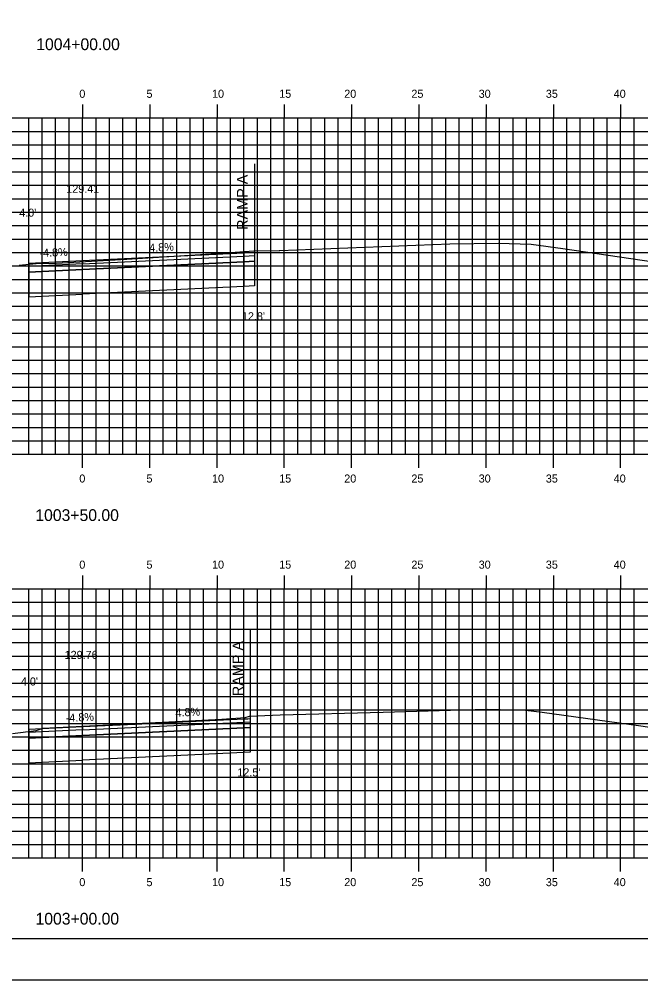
# Model space of a CAD drawing. Extents: x 851073 to 851245, y 365624 to 365734.
# Drawn here: x 851151.5 to 851197.8, y 365624 to 365695.4 of the extents above; entities that cross this region are included whole.
import ezdxf

# ---------------------------------------------------------------- set-up
doc = ezdxf.new("R2010")
doc.units = 0
for name, color, linetype in [('ANNOTATION', 7, 'Continuous'), ('BORDER', 7, 'Continuous'), ('D_Roadway_Centerline', 7, 'Continuous'), ('D_Roadway_Centerline_Text', 7, 'Continuous'), ('D_Roadway_Edge_Shoulder', 7, 'Continuous'), ('D_Roadway_Pavement', 7, 'Continuous'), ('D_Roadway_SubGrade', 7, 'Continuous'), ('D_Text_Standard', 7, 'Continuous'), ('H_V ANNOTATION', 7, 'Continuous'), ('M_Roadway_Centerline', 7, 'Continuous'), ('MAJOR', 7, 'Continuous'), ('MINOR', 7, 'Continuous'), ('PLOT BOUNDARY', 7, 'Continuous'), ('S_Roadway_Centerline', 7, 'Continuous')]:
    doc.layers.add(name, color=color, linetype=linetype)

msp = doc.modelspace()

# ---------------------------------------------------------------- linework, layer by layer
at = {"layer": 'BORDER'}
msp.add_lwpolyline([(851081.253, 365627.027), (851241.253, 365627.027), (851241.253, 365732.027), (851081.253, 365732.027)], close=True, dxfattribs=at)
at = {"layer": 'D_Roadway_Centerline'}
for points in [[(851152.252, 365677.242), (851156.253, 365677.434), (851156.257, 365677.434), (851168.253, 365678.01), (851169.039, 365678.048)], [(851152.252, 365642.595), (851156.252, 365642.787), (851160.165, 365642.975), (851168.244, 365643.362), (851168.252, 365643.363), (851168.549, 365643.377), (851168.706, 365643.384)]]:
    msp.add_lwpolyline(points, dxfattribs=at)
at = {"layer": 'D_Roadway_Edge_Shoulder'}
for p, q in [((851168.253, 365678.01), (851168.253, 365677.76)), ((851156.253, 365677.434), (851156.253, 365677.184)), ((851168.252, 365643.363), (851168.252, 365643.113)), ((851156.252, 365642.787), (851156.252, 365642.537))]:
    msp.add_line(p, q, dxfattribs=at)
at = {"layer": 'D_Roadway_Pavement'}
for points in [[(851156.251, 365677.184), (851168.251, 365677.76), (851168.251, 365677.343), (851156.251, 365676.767)], [(851156.251, 365677.184), (851152.251, 365676.992), (851152.251, 365676.575), (851156.251, 365676.767)], [(851156.251, 365642.537), (851168.251, 365643.113), (851168.251, 365642.696), (851156.251, 365642.12)], [(851156.251, 365642.537), (851152.25, 365642.345), (851152.25, 365641.928), (851156.251, 365642.12)]]:
    msp.add_lwpolyline(points, close=True, dxfattribs=at)
for points in [[(851169.038, 365677.381), (851168.251, 365677.343), (851168.251, 365677.76), (851169.038, 365677.798)], [(851168.707, 365642.718), (851168.251, 365642.696), (851168.251, 365643.113), (851168.707, 365643.135)]]:
    msp.add_lwpolyline(points, dxfattribs=at)
at = {"layer": 'D_Roadway_SubGrade'}
for p, q in [((851169.038, 365684.628), (851169.038, 365677.881)), ((851169.038, 365677.881), (851169.038, 365675.548)), ((851168.707, 365649.965), (851168.707, 365643.218)), ((851168.707, 365643.218), (851168.707, 365640.885))]:
    msp.add_line(p, q, dxfattribs=at)
for points in [[(851156.251, 365676.767), (851152.251, 365676.575), (851152.251, 365677.075), (851152.251, 365677.242), (851152.251, 365674.742), (851156.251, 365674.934)], [(851156.251, 365676.767), (851168.251, 365677.343), (851168.251, 365675.51), (851156.251, 365674.934)], [(851156.251, 365642.12), (851152.25, 365641.928), (851152.25, 365642.428), (851152.25, 365642.595), (851152.25, 365640.095), (851156.251, 365640.287)], [(851156.251, 365642.12), (851168.251, 365642.696), (851168.251, 365640.863), (851156.251, 365640.287)]]:
    msp.add_lwpolyline(points, close=True, dxfattribs=at)
for points in [[(851169.038, 365675.548), (851168.251, 365675.51), (851168.251, 365677.343), (851169.038, 365677.381)], [(851168.707, 365640.885), (851168.251, 365640.863), (851168.251, 365642.696), (851168.707, 365642.718)]]:
    msp.add_lwpolyline(points, dxfattribs=at)
at = {"layer": 'MAJOR'}
for p, q in [((851156.253, 365689.029), (851156.253, 365688.027)), ((851161.253, 365689.029), (851161.253, 365688.027)), ((851166.253, 365689.029), (851166.253, 365688.027)), ((851171.253, 365689.029), (851171.253, 365688.027)), ((851176.253, 365689.029), (851176.253, 365688.027)), ((851181.253, 365689.029), (851181.253, 365688.027)), ((851186.253, 365689.029), (851186.253, 365688.027)), ((851191.253, 365689.029), (851191.253, 365688.027)), ((851196.253, 365689.029), (851196.253, 365688.027)), ((851086.253, 365688.027), (851226.253, 365688.027)), ((851086.253, 365688.027), (851226.253, 365688.027)), ((851156.253, 365663.027), (851156.253, 365688.027)), ((851161.253, 365663.027), (851161.253, 365688.027)), ((851166.253, 365663.027), (851166.253, 365688.027)), ((851171.253, 365663.027), (851171.253, 365688.027)), ((851176.253, 365663.027), (851176.253, 365688.027)), ((851181.253, 365663.027), (851181.253, 365688.027)), ((851186.253, 365663.027), (851186.253, 365688.027)), ((851191.253, 365663.027), (851191.253, 365688.027)), ((851196.253, 365663.027), (851196.253, 365688.027)), ((851086.253, 365683.027), (851226.253, 365683.027)), ((851086.253, 365678.027), (851226.253, 365678.027)), ((851086.253, 365673.027), (851226.253, 365673.027)), ((851086.253, 365668.027), (851226.253, 365668.027)), ((851086.253, 365663.027), (851226.253, 365663.027)), ((851086.253, 365663.027), (851226.253, 365663.027)), ((851156.253, 365662.025), (851156.253, 365663.027)), ((851161.253, 365662.025), (851161.253, 365663.027)), ((851166.253, 365662.025), (851166.253, 365663.027)), ((851171.253, 365662.025), (851171.253, 365663.027)), ((851176.253, 365662.025), (851176.253, 365663.027)), ((851181.253, 365662.025), (851181.253, 365663.027)), ((851186.253, 365662.025), (851186.253, 365663.027)), ((851191.253, 365662.025), (851191.253, 365663.027)), ((851196.253, 365662.025), (851196.253, 365663.027)), ((851156.253, 365654.029), (851156.253, 365653.027)), ((851161.253, 365654.029), (851161.253, 365653.027)), ((851166.253, 365654.029), (851166.253, 365653.027)), ((851171.253, 365654.029), (851171.253, 365653.027)), ((851176.253, 365654.029), (851176.253, 365653.027)), ((851181.253, 365654.029), (851181.253, 365653.027)), ((851186.253, 365654.029), (851186.253, 365653.027)), ((851191.253, 365654.029), (851191.253, 365653.027)), ((851196.253, 365654.029), (851196.253, 365653.027)), ((851086.253, 365653.027), (851226.253, 365653.027)), ((851086.253, 365653.027), (851226.253, 365653.027)), ((851156.253, 365633.027), (851156.253, 365653.027)), ((851161.253, 365633.027), (851161.253, 365653.027)), ((851166.253, 365633.027), (851166.253, 365653.027)), ((851171.253, 365633.027), (851171.253, 365653.027)), ((851176.253, 365633.027), (851176.253, 365653.027)), ((851181.253, 365633.027), (851181.253, 365653.027)), ((851186.253, 365633.027), (851186.253, 365653.027)), ((851191.253, 365633.027), (851191.253, 365653.027)), ((851196.253, 365633.027), (851196.253, 365653.027)), ((851086.253, 365648.027), (851226.253, 365648.027)), ((851086.253, 365643.027), (851226.253, 365643.027)), ((851086.253, 365638.027), (851226.253, 365638.027)), ((851086.253, 365633.027), (851226.253, 365633.027)), ((851086.253, 365633.027), (851226.253, 365633.027)), ((851156.253, 365632.025), (851156.253, 365633.027)), ((851161.253, 365632.025), (851161.253, 365633.027)), ((851166.253, 365632.025), (851166.253, 365633.027)), ((851171.253, 365632.025), (851171.253, 365633.027)), ((851176.253, 365632.025), (851176.253, 365633.027)), ((851181.253, 365632.025), (851181.253, 365633.027)), ((851186.253, 365632.025), (851186.253, 365633.027)), ((851191.253, 365632.025), (851191.253, 365633.027)), ((851196.253, 365632.025), (851196.253, 365633.027))]:
    msp.add_line(p, q, dxfattribs=at)
at = {"layer": 'MINOR'}
for p, q in [((851152.253, 365663.027), (851152.253, 365688.027)), ((851153.253, 365663.027), (851153.253, 365688.027)), ((851154.253, 365663.027), (851154.253, 365688.027)), ((851155.253, 365663.027), (851155.253, 365688.027)), ((851157.253, 365663.027), (851157.253, 365688.027)), ((851158.253, 365663.027), (851158.253, 365688.027)), ((851159.253, 365663.027), (851159.253, 365688.027)), ((851160.253, 365663.027), (851160.253, 365688.027)), ((851162.253, 365663.027), (851162.253, 365688.027)), ((851163.253, 365663.027), (851163.253, 365688.027)), ((851164.253, 365663.027), (851164.253, 365688.027)), ((851165.253, 365663.027), (851165.253, 365688.027)), ((851167.253, 365663.027), (851167.253, 365688.027)), ((851168.253, 365663.027), (851168.253, 365688.027)), ((851169.253, 365663.027), (851169.253, 365688.027)), ((851170.253, 365663.027), (851170.253, 365688.027)), ((851172.253, 365663.027), (851172.253, 365688.027)), ((851173.253, 365663.027), (851173.253, 365688.027)), ((851174.253, 365663.027), (851174.253, 365688.027)), ((851175.253, 365663.027), (851175.253, 365688.027)), ((851177.253, 365663.027), (851177.253, 365688.027)), ((851178.253, 365663.027), (851178.253, 365688.027)), ((851179.253, 365663.027), (851179.253, 365688.027)), ((851180.253, 365663.027), (851180.253, 365688.027)), ((851182.253, 365663.027), (851182.253, 365688.027)), ((851183.253, 365663.027), (851183.253, 365688.027)), ((851184.253, 365663.027), (851184.253, 365688.027)), ((851185.253, 365663.027), (851185.253, 365688.027)), ((851187.253, 365663.027), (851187.253, 365688.027)), ((851188.253, 365663.027), (851188.253, 365688.027)), ((851189.253, 365663.027), (851189.253, 365688.027)), ((851190.253, 365663.027), (851190.253, 365688.027)), ((851192.253, 365663.027), (851192.253, 365688.027)), ((851193.253, 365663.027), (851193.253, 365688.027)), ((851194.253, 365663.027), (851194.253, 365688.027)), ((851195.253, 365663.027), (851195.253, 365688.027)), ((851197.253, 365663.027), (851197.253, 365688.027)), ((851086.253, 365687.027), (851226.253, 365687.027)), ((851086.253, 365686.027), (851226.253, 365686.027)), ((851086.253, 365685.027), (851226.253, 365685.027)), ((851086.253, 365684.027), (851226.253, 365684.027)), ((851086.253, 365682.027), (851226.253, 365682.027)), ((851086.253, 365681.027), (851226.253, 365681.027)), ((851086.253, 365680.027), (851226.253, 365680.027)), ((851086.253, 365679.027), (851226.253, 365679.027)), ((851086.253, 365677.027), (851226.253, 365677.027)), ((851086.253, 365676.027), (851226.253, 365676.027)), ((851086.253, 365675.027), (851226.253, 365675.027)), ((851086.253, 365674.027), (851226.253, 365674.027)), ((851086.253, 365672.027), (851226.253, 365672.027)), ((851086.253, 365671.027), (851226.253, 365671.027)), ((851086.253, 365670.027), (851226.253, 365670.027)), ((851086.253, 365669.027), (851226.253, 365669.027)), ((851086.253, 365667.027), (851226.253, 365667.027)), ((851086.253, 365666.027), (851226.253, 365666.027)), ((851086.253, 365665.027), (851226.253, 365665.027)), ((851086.253, 365664.027), (851226.253, 365664.027)), ((851152.253, 365633.027), (851152.253, 365653.027)), ((851153.253, 365633.027), (851153.253, 365653.027)), ((851154.253, 365633.027), (851154.253, 365653.027)), ((851155.253, 365633.027), (851155.253, 365653.027)), ((851157.253, 365633.027), (851157.253, 365653.027)), ((851158.253, 365633.027), (851158.253, 365653.027)), ((851159.253, 365633.027), (851159.253, 365653.027)), ((851160.253, 365633.027), (851160.253, 365653.027)), ((851162.253, 365633.027), (851162.253, 365653.027)), ((851163.253, 365633.027), (851163.253, 365653.027)), ((851164.253, 365633.027), (851164.253, 365653.027)), ((851165.253, 365633.027), (851165.253, 365653.027)), ((851167.253, 365633.027), (851167.253, 365653.027)), ((851168.253, 365633.027), (851168.253, 365653.027)), ((851169.253, 365633.027), (851169.253, 365653.027)), ((851170.253, 365633.027), (851170.253, 365653.027)), ((851172.253, 365633.027), (851172.253, 365653.027)), ((851173.253, 365633.027), (851173.253, 365653.027)), ((851174.253, 365633.027), (851174.253, 365653.027)), ((851175.253, 365633.027), (851175.253, 365653.027)), ((851177.253, 365633.027), (851177.253, 365653.027)), ((851178.253, 365633.027), (851178.253, 365653.027)), ((851179.253, 365633.027), (851179.253, 365653.027)), ((851180.253, 365633.027), (851180.253, 365653.027)), ((851182.253, 365633.027), (851182.253, 365653.027)), ((851183.253, 365633.027), (851183.253, 365653.027)), ((851184.253, 365633.027), (851184.253, 365653.027)), ((851185.253, 365633.027), (851185.253, 365653.027)), ((851187.253, 365633.027), (851187.253, 365653.027)), ((851188.253, 365633.027), (851188.253, 365653.027)), ((851189.253, 365633.027), (851189.253, 365653.027)), ((851190.253, 365633.027), (851190.253, 365653.027)), ((851192.253, 365633.027), (851192.253, 365653.027)), ((851193.253, 365633.027), (851193.253, 365653.027)), ((851194.253, 365633.027), (851194.253, 365653.027)), ((851195.253, 365633.027), (851195.253, 365653.027)), ((851197.253, 365633.027), (851197.253, 365653.027)), ((851086.253, 365652.027), (851226.253, 365652.027)), ((851086.253, 365651.027), (851226.253, 365651.027)), ((851086.253, 365650.027), (851226.253, 365650.027)), ((851086.253, 365649.027), (851226.253, 365649.027)), ((851086.253, 365647.027), (851226.253, 365647.027)), ((851086.253, 365646.027), (851226.253, 365646.027)), ((851086.253, 365645.027), (851226.253, 365645.027)), ((851086.253, 365644.027), (851226.253, 365644.027)), ((851086.253, 365642.027), (851226.253, 365642.027)), ((851086.253, 365641.027), (851226.253, 365641.027)), ((851086.253, 365640.027), (851226.253, 365640.027)), ((851086.253, 365639.027), (851226.253, 365639.027)), ((851086.253, 365637.027), (851226.253, 365637.027)), ((851086.253, 365636.027), (851226.253, 365636.027)), ((851086.253, 365635.027), (851226.253, 365635.027)), ((851086.253, 365634.027), (851226.253, 365634.027))]:
    msp.add_line(p, q, dxfattribs=at)
at = {"layer": 'PLOT BOUNDARY'}
msp.add_lwpolyline([(851073.159, 365623.968), (851243.159, 365623.968), (851243.159, 365733.968), (851073.159, 365733.968)], close=True, dxfattribs=at)
at = {"layer": 'S_Roadway_Centerline'}
for points in [[(851151.531, 365677.075), (851152.804, 365677.205), (851154.297, 365677.225), (851159.548, 365677.54), (851166.187, 365677.959), (851168.995, 365678.156), (851170.857, 365678.178), (851170.921, 365678.18), (851183.549, 365678.676), (851187.145, 365678.732), (851189.599, 365678.645), (851191.949, 365678.333), (851199.532, 365677.211), (851208.051, 365675.806), (851223.18, 365673.214), (851225.062, 365672.879), (851226.253, 365673.336)], [(851151.044, 365642.279), (851152.802, 365642.489), (851153.315, 365642.683), (851166.611, 365643.347), (851168.344, 365643.455), (851168.666, 365643.558), (851170.94, 365643.653), (851178.594, 365643.862), (851183.609, 365644.018), (851186.36, 365644.087), (851189.184, 365644.011), (851190.428, 365643.857), (851197.751, 365642.835), (851205.186, 365641.722), (851217.642, 365639.516), (851222.712, 365638.535), (851223.393, 365638.547), (851226.253, 365639.478)]]:
    msp.add_lwpolyline(points, dxfattribs=at)

# ---------------------------------------------------------------- texts
at = {"layer": 'ANNOTATION'}
for s, height, rotation, p in [('RAMP A', 0.8, 90, (851168.532, 365679.712)), ('-4.8%', 0.6, 2.74786, (851153.062, 365677.682)), ('4.8%', 0.6, 2.74811, (851161.223, 365678.074)), ('RAMP A', 0.8, 90, (851168.2, 365645.049)), ('4.8%', 0.6, 2.74814, (851163.173, 365643.52)), ('-4.8%', 0.6, 2.7483, (851155.017, 365643.129))]:
    msp.add_text(s, height=height, rotation=rotation, dxfattribs=at).set_placement(p)
at = {"layer": 'D_Roadway_Centerline'}
for s, p in [('C', (851156.247, 365677.434)), ('L', (851156.253, 365677.426)), ('C', (851156.247, 365642.787)), ('L', (851156.252, 365642.779))]:
    msp.add_text(s, height=0.0146, dxfattribs=at).set_placement(p)
at = {"layer": 'D_Roadway_Centerline_Text'}
for s, p in [('129.41', (851155.043, 365682.466)), ('129.76', (851154.92, 365647.819))]:
    msp.add_text(s, height=0.6, dxfattribs=at).set_placement(p)
at = {"layer": 'D_Text_Standard'}
for s, p in [("4.0'", (851151.546, 365680.689)), ("12.8'", (851168.1, 365672.988)), ("4.0'", (851151.668, 365645.841)), ("12.5'", (851167.758, 365639.086))]:
    msp.add_text(s, height=0.6, dxfattribs=at).set_placement(p)
at = {"layer": 'H_V ANNOTATION'}
for s, height, p in [('1004+00.00', 0.875, (851152.811, 365693.07)), ('0', 0.6, (851156.012, 365689.527)), ('5', 0.6, (851161.004, 365689.527)), ('10', 0.6, (851165.878, 365689.527)), ('15', 0.6, (851170.87, 365689.527)), ('20', 0.6, (851175.707, 365689.527)), ('25', 0.6, (851180.699, 365689.527)), ('30', 0.6, (851185.701, 365689.527)), ('35', 0.6, (851190.693, 365689.527)), ('40', 0.6, (851195.739, 365689.527)), ('0', 0.6, (851156.012, 365660.927)), ('5', 0.6, (851161.004, 365660.927)), ('10', 0.6, (851165.878, 365660.927)), ('15', 0.6, (851170.87, 365660.927)), ('20', 0.6, (851175.707, 365660.927)), ('25', 0.6, (851180.699, 365660.927)), ('30', 0.6, (851185.701, 365660.927)), ('35', 0.6, (851190.693, 365660.927)), ('40', 0.6, (851195.739, 365660.927)), ('1003+50.00', 0.875, (851152.741, 365658.07)), ('0', 0.6, (851156.012, 365654.527)), ('5', 0.6, (851161.004, 365654.527)), ('10', 0.6, (851165.878, 365654.527)), ('15', 0.6, (851170.87, 365654.527)), ('20', 0.6, (851175.707, 365654.527)), ('25', 0.6, (851180.699, 365654.527)), ('30', 0.6, (851185.701, 365654.527)), ('35', 0.6, (851190.693, 365654.527)), ('40', 0.6, (851195.739, 365654.527)), ('0', 0.6, (851156.012, 365630.927)), ('5', 0.6, (851161.004, 365630.927)), ('10', 0.6, (851165.878, 365630.927)), ('15', 0.6, (851170.87, 365630.927)), ('20', 0.6, (851175.707, 365630.927)), ('25', 0.6, (851180.699, 365630.927)), ('30', 0.6, (851185.701, 365630.927)), ('35', 0.6, (851190.693, 365630.927)), ('40', 0.6, (851195.739, 365630.927)), ('1003+00.00', 0.875, (851152.757, 365628.07))]:
    msp.add_text(s, height=height, dxfattribs=at).set_placement(p)
at = {"layer": 'M_Roadway_Centerline'}
for s, p in [('C', (851168.99, 365678.156)), ('L', (851168.995, 365678.148)), ('C', (851168.66, 365643.558)), ('L', (851168.666, 365643.551))]:
    msp.add_text(s, height=0.0146, dxfattribs=at).set_placement(p)

doc.saveas('drawing.dxf')
